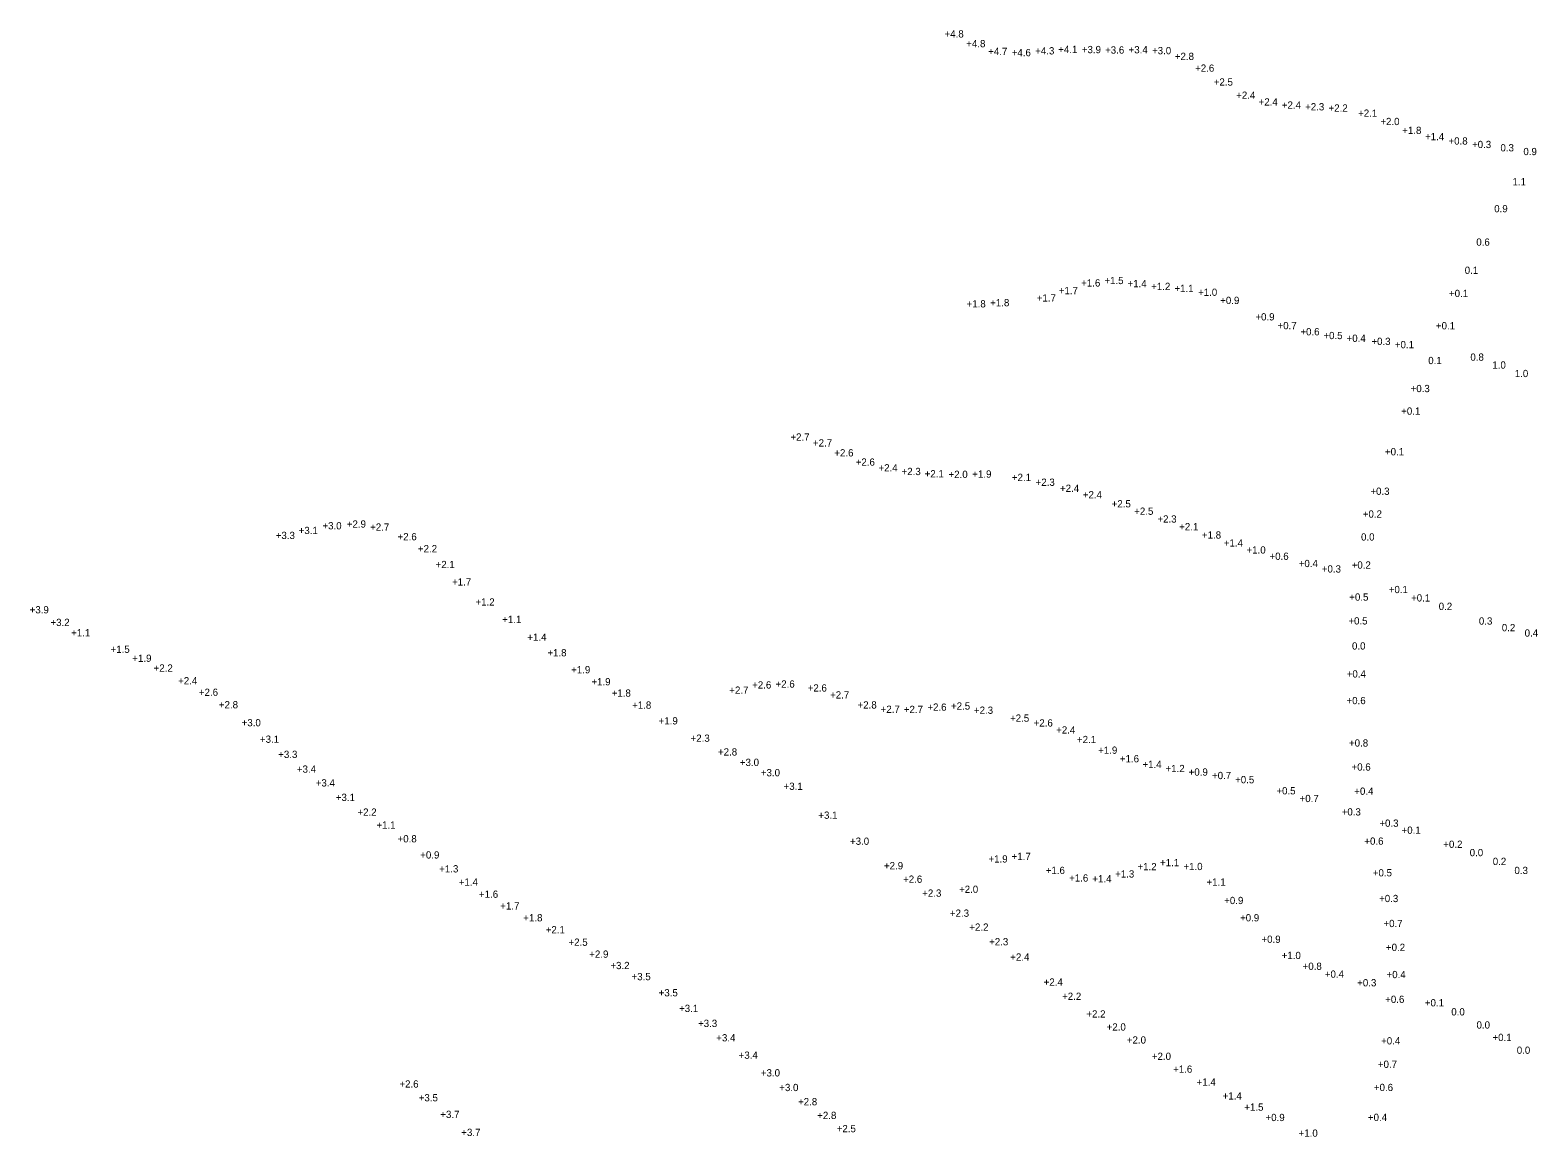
# Model space of a CAD drawing. Extents: x 837127 to 848654, y 3074248 to 3079868.
# Drawn here: x 842266 to 842915, y 3078515 to 3078992 of the extents above; entities that cross this region are included whole.
import ezdxf

# ---------------------------------------------------------------- set-up
doc = ezdxf.new("R2010")
doc.units = 0
doc.layers.add('V-HYDS-SOUN', color=7, linetype='Continuous')

msp = doc.modelspace()

# ---------------------------------------------------------------- texts
at = {"layer": 'V-HYDS-SOUN'}
for s, p in [('+4.8 ', (842659.55, 3078988.42)), ('+4.8 ', (842668.9, 3078984.22)), ('+4.7 ', (842678.36, 3078980.89)), ('+4.6 ', (842688.48, 3078980.35)), ('+4.3 ', (842698.6, 3078981.13)), ('+4.1 ', (842708.53, 3078981.73)), ('+3.9 ', (842718.69, 3078981.67)), ('+3.6 ', (842728.71, 3078981.49)), ('+3.4 ', (842738.84, 3078981.6)), ('+3.0 ', (842748.94, 3078981.21)), ('+2.8 ', (842758.77, 3078978.73)), ('+2.6 ', (842767.5, 3078973.67)), ('+2.5 ', (842775.54, 3078967.7)), ('+2.4 ', (842785.2, 3078962)), ('+2.4 ', (842794.87, 3078959.1)), ('+2.4 ', (842804.88, 3078957.75)), ('+2.3 ', (842814.9, 3078957)), ('+2.2 ', (842825.01, 3078956.47)), ('+2.1 ', (842837.74, 3078954.26)), ('+2.0 ', (842847.33, 3078950.67)), ('+1.8 ', (842856.76, 3078946.86)), ('+1.4 ', (842866.58, 3078944.16)), ('+0.8 ', (842876.69, 3078942.27)), ('+0.3 ', (842886.83, 3078940.77)), ('0.3', (842899.07, 3078939.35)), ('0.9', (842908.96, 3078937.73)), ('1.1', (842904.26, 3078924.72)), ('0.9', (842896.39, 3078913.11)), ('0.6', (842888.67, 3078898.7)), ('0.1', (842883.68, 3078886.55)), ('+1.7 ', (842708.77, 3078877.8)), ('+1.6 ', (842718.41, 3078881.1)), ('+1.5 ', (842728.42, 3078882.15)), ('+1.4 ', (842738.39, 3078880.81)), ('+1.2 ', (842748.58, 3078879.59)), ('+1.1 ', (842758.59, 3078878.75)), ('+1.0 ', (842768.78, 3078877.08)), ('+0.1 ', (842876.9, 3078876.57)), ('+1.8 ', (842669.04, 3078872.1)), ('+1.8 ', (842679.2, 3078872.59)), ('+1.7 ', (842699.27, 3078874.62)), ('+0.9 ', (842778.32, 3078873.58)), ('+0.9 ', (842793.48, 3078866.49)), ('+0.7 ', (842803.03, 3078862.71)), ('+0.6 ', (842812.87, 3078860.08)), ('+0.5 ', (842822.79, 3078858.44)), ('+0.4 ', (842832.78, 3078857.27)), ('+0.1 ', (842871.27, 3078862.66)), ('+0.3 ', (842843.47, 3078855.92)), ('+0.1 ', (842853.57, 3078854.51)), ('0.1', (842867.96, 3078847.67)), ('0.8', (842886.12, 3078849.13)), ('1.0', (842895.59, 3078845.73)), ('1.0', (842905.25, 3078842.07)), ('+0.3 ', (842860.38, 3078835.59)), ('+0.1 ', (842856.31, 3078825.88)), ('+2.7 ', (842593.12, 3078814.7)), ('+2.7 ', (842602.84, 3078812.17)), ('+2.6 ', (842612.04, 3078807.88)), ('+0.1 ', (842849.32, 3078808.38)), ('+2.6 ', (842621.25, 3078803.91)), ('+2.4 ', (842631.06, 3078801.41)), ('+2.3 ', (842641.02, 3078799.85)), ('+2.1 ', (842650.97, 3078798.87)), ('+2.0 ', (842661.26, 3078798.6)), ('+1.9 ', (842671.49, 3078798.75)), ('+2.1 ', (842688.56, 3078797.3)), ('+2.3 ', (842698.79, 3078795.22)), ('+2.4 ', (842709.29, 3078792.6)), ('+2.4 ', (842719.13, 3078789.84)), ('+2.5 ', (842731.55, 3078785.93)), ('+0.3 ', (842843.03, 3078791.34)), ('+2.5 ', (842741.27, 3078782.73)), ('+2.3 ', (842751.26, 3078779.38)), ('+0.2 ', (842839.77, 3078781.51)), ('+3.3 ', (842371.35, 3078772.3)), ('+3.1 ', (842381.22, 3078774.43)), ('+3.0 ', (842391.47, 3078776.46)), ('+2.9 ', (842401.97, 3078777.21)), ('+2.7 ', (842412.03, 3078775.9)), ('+2.1 ', (842760.66, 3078776.05)), ('+1.8 ', (842770.45, 3078772.48)), ('+2.6 ', (842423.84, 3078771.75)), ('+2.2 ', (842432.62, 3078766.56)), ('+1.4 ', (842779.87, 3078769.03)), ('+1.0 ', (842789.66, 3078766.03)), (' 0.0', (842837.84, 3078771.63)), ('+2.1 ', (842440.23, 3078759.76)), ('+0.6 ', (842799.57, 3078763.31)), ('+0.4 ', (842812.15, 3078760.2)), ('+0.2 ', (842834.98, 3078759.54)), ('+0.3 ', (842822.1, 3078757.85)), ('+1.7 ', (842447.31, 3078752.26)), ('+0.1 ', (842850.95, 3078748.98)), ('+3.9 ', (842265.31, 3078740.26)), ('+1.2 ', (842457.41, 3078743.61)), ('+0.5 ', (842833.93, 3078745.74)), ('+0.1 ', (842860.56, 3078745.37)), ('0.2', (842872.47, 3078741.73)), ('+3.2 ', (842274.29, 3078734.81)), ('+1.1 ', (842468.94, 3078736.12)), ('+0.5 ', (842833.55, 3078735.47)), ('0.3', (842889.78, 3078735.41)), ('+1.1 ', (842283.18, 3078730.35)), ('+1.4 ', (842479.76, 3078728.44)), ('0.2', (842899.67, 3078732.55)), ('0.4', (842909.5, 3078730.24)), ('+1.5 ', (842300.17, 3078723.22)), ('+1.8 ', (842488.39, 3078721.73)), (' 0.0', (842833.94, 3078724.67)), ('+1.9 ', (842309.54, 3078719.37)), ('+2.2 ', (842318.73, 3078715.14)), ('+1.9 ', (842498.63, 3078714.43)), ('+2.4 ', (842329.28, 3078709.65)), ('+1.9 ', (842507.35, 3078709.24)), ('+2.6 ', (842576.63, 3078707.86)), ('+2.6 ', (842586.72, 3078708.26)), ('+0.4 ', (842832.84, 3078712.61)), ('+2.6 ', (842338.24, 3078704.7)), ('+1.8 ', (842516.11, 3078704.35)), ('+2.7 ', (842566.79, 3078705.62)), ('+2.6 ', (842600.57, 3078706.56)), ('+2.7 ', (842610.21, 3078703.57)), ('+0.6 ', (842832.75, 3078701.12)), ('+2.8 ', (842346.85, 3078699.32)), ('+1.8 ', (842524.91, 3078699.17)), ('+2.8 ', (842622.05, 3078699.25)), ('+2.7 ', (842632, 3078697.38)), ('+2.7 ', (842642, 3078697.31)), ('+2.6 ', (842652.14, 3078698.3)), ('+2.5 ', (842662.32, 3078698.78)), ('+2.3 ', (842672.21, 3078696.97)), ('+3.0 ', (842356.66, 3078691.6)), ('+1.9 ', (842536.33, 3078692.39)), ('+2.5 ', (842687.76, 3078693.56)), ('+2.6 ', (842697.93, 3078691.49)), ('+2.4 ', (842707.63, 3078688.47)), ('+3.1 ', (842364.55, 3078684.48)), ('+2.3 ', (842550.1, 3078684.92)), ('+2.1 ', (842716.6, 3078684.34)), ('+0.8 ', (842833.82, 3078682.85)), ('+3.3 ', (842372.42, 3078677.95)), ('+2.8 ', (842561.91, 3078679)), ('+1.9 ', (842725.73, 3078679.76)), ('+1.6 ', (842735.09, 3078676.07)), ('+3.4 ', (842380.46, 3078671.59)), ('+3.0 ', (842571.34, 3078674.5)), ('+3.0 ', (842580.38, 3078670.06)), ('+1.4 ', (842744.81, 3078673.63)), ('+1.2 ', (842754.75, 3078671.84)), ('+0.9 ', (842764.73, 3078670.33)), ('+0.7 ', (842774.79, 3078668.83)), ('+0.6 ', (842834.91, 3078672.5)), ('+3.4 ', (842388.59, 3078665.66)), ('+3.1 ', (842590.18, 3078664.2)), ('+0.5 ', (842784.74, 3078667.04)), ('+0.5 ', (842802.53, 3078662.25)), ('+0.4 ', (842836.1, 3078662.08)), ('+3.1 ', (842397.22, 3078659.42)), ('+0.7 ', (842812.53, 3078658.93)), ('+2.2 ', (842406.56, 3078653.06)), ('+3.1 ', (842605.15, 3078651.74)), ('+0.3 ', (842830.67, 3078653.16)), ('+1.1 ', (842414.72, 3078647.49)), ('+0.3 ', (842846.9, 3078648.3)), ('+0.1 ', (842856.47, 3078645.27)), ('+0.8 ', (842423.84, 3078641.57)), ('+3.0 ', (842618.79, 3078640.52)), ('+0.6 ', (842840.43, 3078640.56)), ('+0.2 ', (842874.45, 3078639.22)), ('+0.9 ', (842433.61, 3078634.61)), ('+2.9 ', (842633.44, 3078629.97)), ('+1.9 ', (842678.45, 3078632.88)), ('+1.7 ', (842688.44, 3078633.97)), ('+1.2 ', (842742.67, 3078629.55)), ('+1.1 ', (842752.38, 3078631.29)), ('+1.0 ', (842762.47, 3078629.63)), (' 0.0', (842884.66, 3078635.61)), ('0.2', (842895.77, 3078631.83)), ('+1.3 ', (842441.78, 3078628.62)), ('+1.4 ', (842450.2, 3078622.89)), ('+2.6 ', (842641.67, 3078624.16)), ('+1.6 ', (842703.14, 3078627.95)), ('+1.6 ', (842713.21, 3078624.67)), ('+1.4 ', (842723.22, 3078624.33)), ('+1.3 ', (842733.03, 3078626.41)), ('+1.1 ', (842772.42, 3078622.91)), ('+0.5 ', (842844.08, 3078626.92)), ('0.3', (842905.1, 3078627.93)), ('+1.6 ', (842458.92, 3078617.68)), ('+2.3 ', (842649.92, 3078618.15)), ('+2.0 ', (842665.78, 3078619.79)), ('+1.7 ', (842468.1, 3078612.64)), ('+0.9 ', (842780.04, 3078614.98)), ('+0.3 ', (842846.79, 3078615.83)), ('+1.8 ', (842478.02, 3078607.52)), ('+2.3 ', (842661.85, 3078609.51)), ('+2.2 ', (842670.21, 3078603.5)), ('+0.9 ', (842786.87, 3078607.53)), ('+0.7 ', (842848.68, 3078605.07)), ('+2.1 ', (842487.68, 3078602.38)), ('+2.5 ', (842497.5, 3078597.01)), ('+2.3 ', (842678.74, 3078597.19)), ('+0.9 ', (842796.1, 3078598.27)), ('+2.9 ', (842506.44, 3078591.86)), ('+2.4 ', (842687.86, 3078590.59)), ('+1.0 ', (842804.8, 3078591.29)), ('+0.2 ', (842849.74, 3078594.77)), ('+3.2 ', (842515.54, 3078586.95)), ('+0.8 ', (842813.84, 3078586.63)), ('+3.5 ', (842524.67, 3078582.18)), ('+2.4 ', (842702.25, 3078579.81)), ('+0.4 ', (842823.41, 3078583.25)), ('+0.3 ', (842837.35, 3078579.52)), ('+0.4 ', (842850, 3078583.06)), ('+3.5 ', (842536.35, 3078575.22)), ('+2.2 ', (842710.18, 3078573.69)), ('+0.6 ', (842849.42, 3078572.39)), ('+0.1 ', (842866.51, 3078570.9)), ('+3.1 ', (842545.14, 3078568.48)), ('+2.2 ', (842720.64, 3078566.08)), (' 0.0', (842876.73, 3078566.99)), ('+3.3 ', (842553.32, 3078562.02)), ('+2.0 ', (842729.39, 3078560.46)), (' 0.0', (842887.61, 3078561.33)), ('+3.4 ', (842561.18, 3078555.8)), ('+2.0 ', (842738.09, 3078554.86)), ('+0.4 ', (842847.66, 3078554.51)), ('+0.1 ', (842895.64, 3078555.97)), ('+3.4 ', (842570.81, 3078548.31)), ('+2.0 ', (842748.87, 3078547.83)), (' 0.0', (842904.95, 3078550.46)), ('+3.0 ', (842580.39, 3078540.7)), ('+1.6 ', (842758.03, 3078542.3)), ('+0.7 ', (842846.27, 3078544.4)), ('+2.6 ', (842424.63, 3078535.9)), ('+3.0 ', (842588.32, 3078534.39)), ('+1.4 ', (842768.16, 3078536.71)), ('+0.6 ', (842844.55, 3078534.41)), ('+3.5 ', (842432.96, 3078529.98)), ('+2.8 ', (842596.41, 3078528.26)), ('+1.4 ', (842779.38, 3078530.75)), ('+1.5 ', (842788.71, 3078525.93)), ('+3.7 ', (842442.26, 3078522.81)), ('+2.8 ', (842604.67, 3078522.35)), ('+0.9 ', (842797.85, 3078521.47)), ('+0.4 ', (842841.97, 3078521.51)), ('+3.7 ', (842451.3, 3078515.04)), ('+2.5 ', (842613.07, 3078516.66)), ('+1.0 ', (842812.1, 3078514.72))]:
    msp.add_text(s, height=3.125, dxfattribs=at).set_placement(p)

doc.saveas('drawing.dxf')
